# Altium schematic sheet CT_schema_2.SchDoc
size 461 x 297 mm
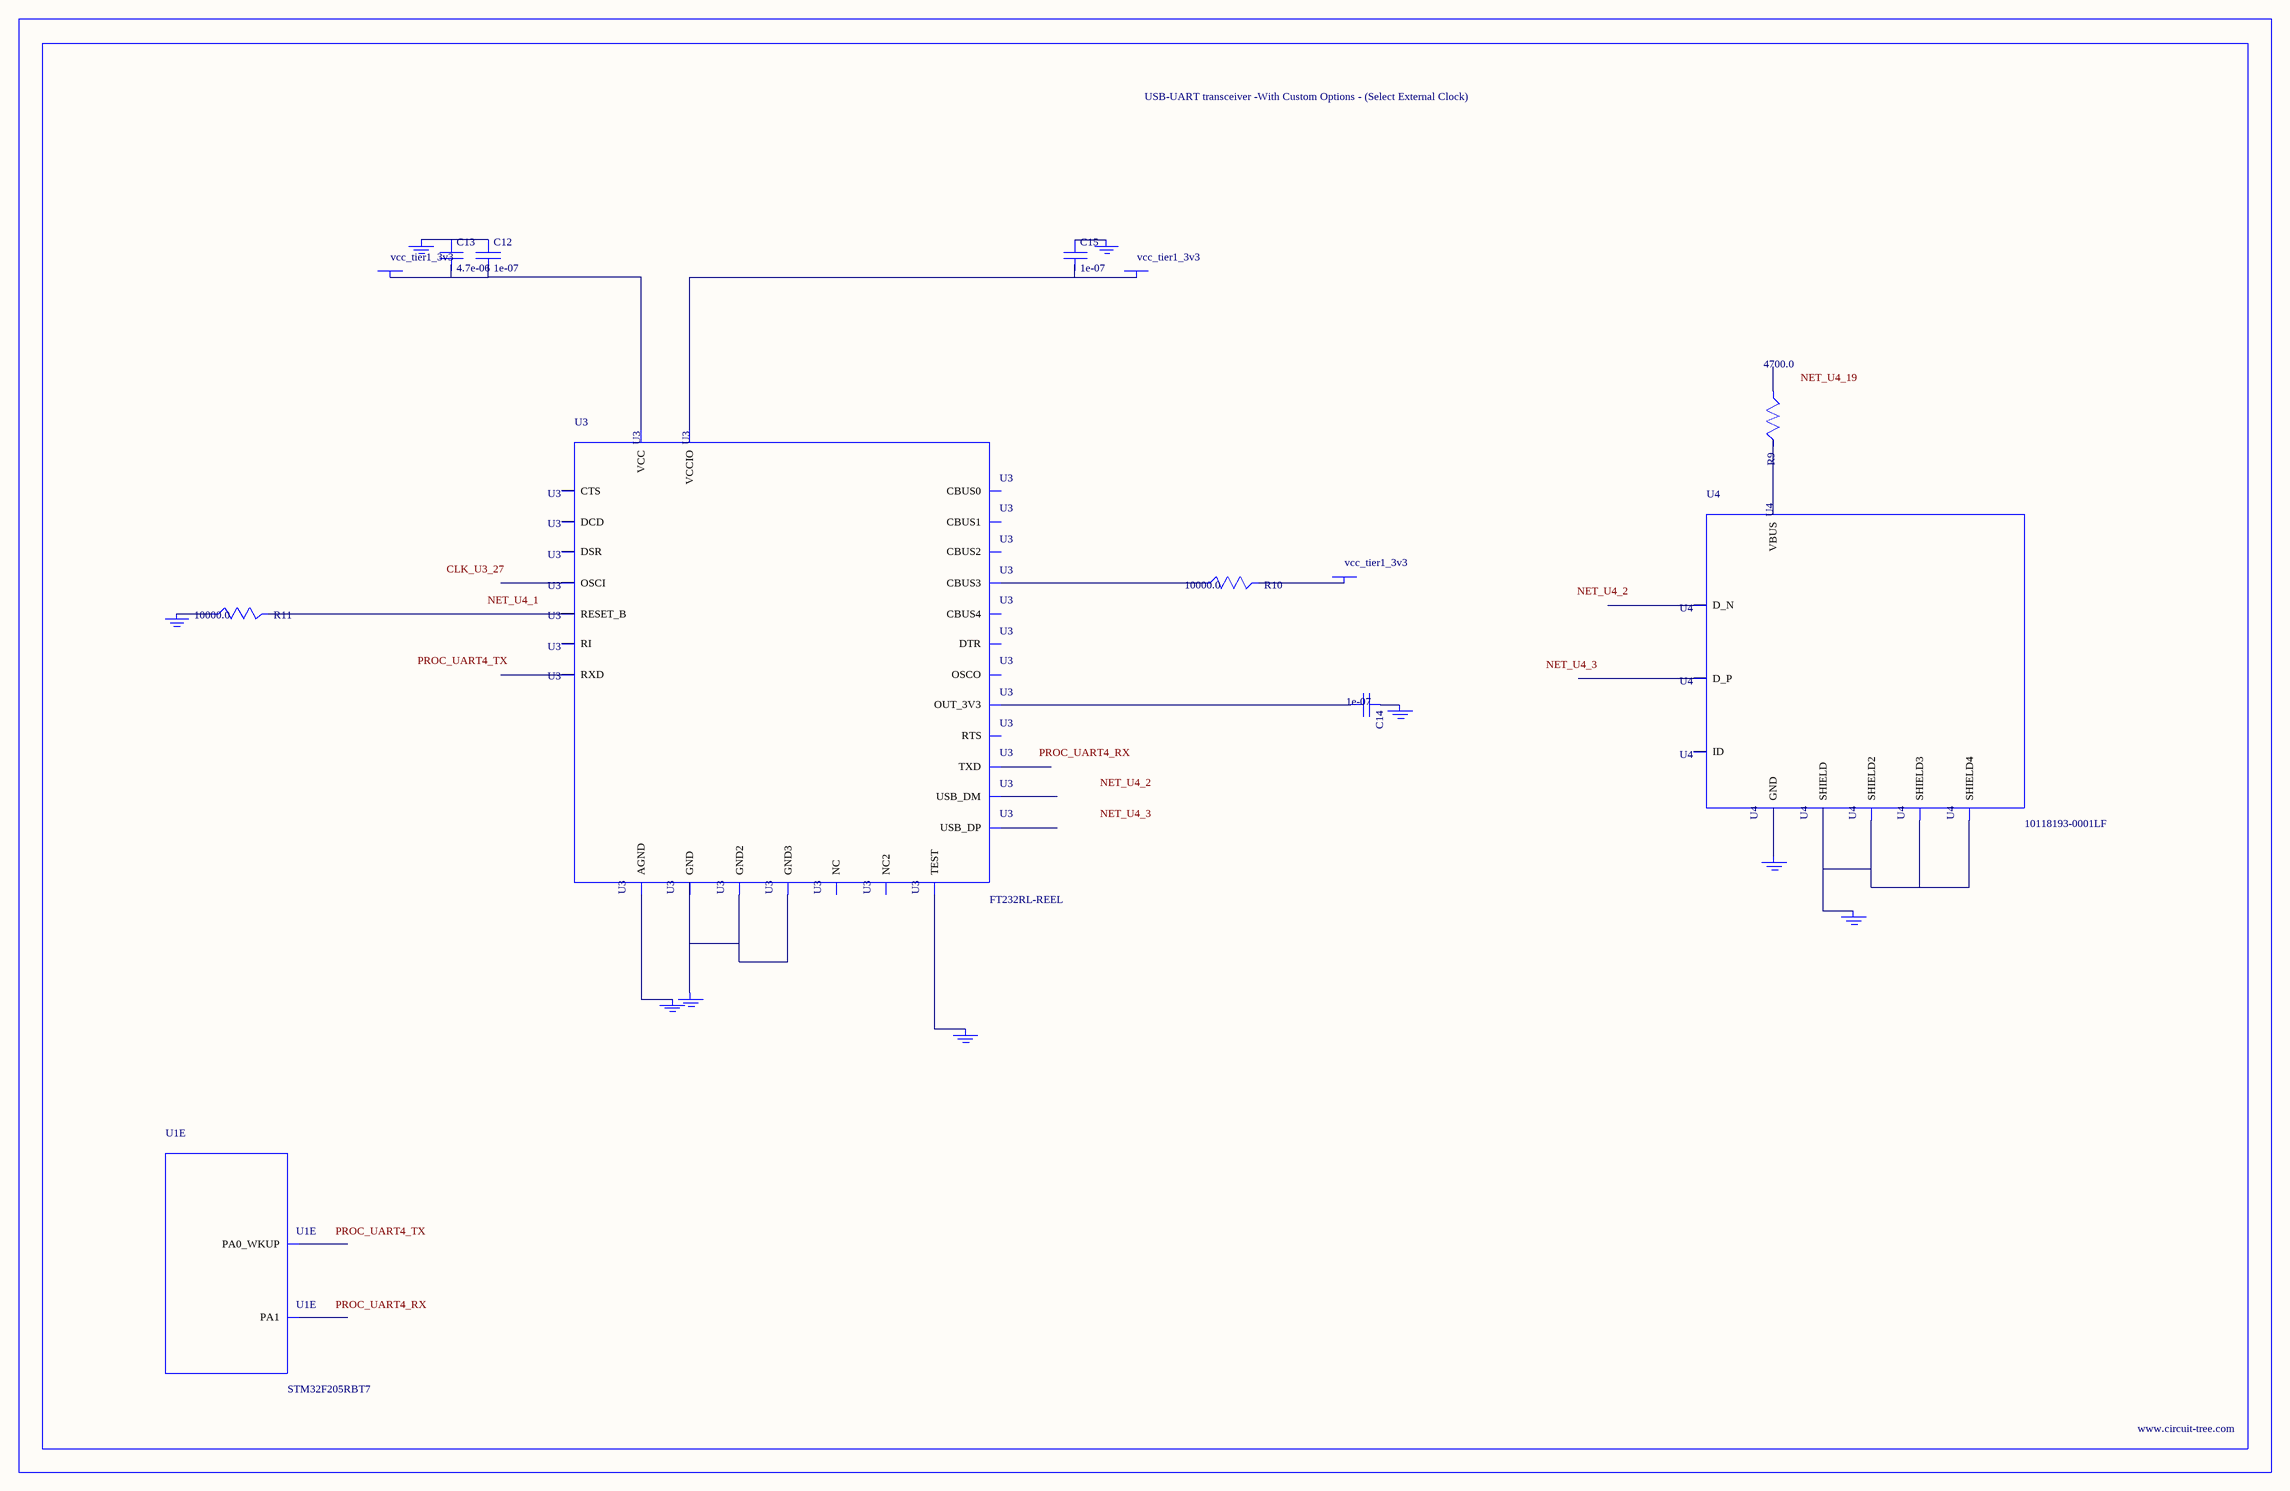
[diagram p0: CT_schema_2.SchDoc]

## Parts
BORDER1  (no value)
C12  1e-07  [C0402]
C13  4.7e-06  [C0805]
C14  1e-07  [C0402]
C15  1e-07  [C0402]
GND_INSTANCE_1_0  (no value)
GND_INSTANCE_1_1  (no value)
GND_INSTANCE_1_2  (no value)
GND_INSTANCE_1_3  (no value)
GND_INSTANCE_1_4  (no value)
GND_INSTANCE_1_5  (no value)
GND_INSTANCE_1_6  (no value)
GND_INSTANCE_1_7  (no value)
GND_INSTANCE_1_8  (no value)
POWER_INSTANCE_1_0  vcc_tier1_3v3
POWER_INSTANCE_1_1  vcc_tier1_3v3
POWER_INSTANCE_1_2  vcc_tier1_3v3
R9  4700.0  [R0603]
R10  10000.0  [R0603]
R11  10000.0  [R0603]
U1  STM32F205RBT7  [LQFP64]  (part E of 7)
U3  FT232RL-REEL  [SSOP-28]
U4  10118193-0001LF  [FCI_10118193-0001LF]

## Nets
NetC12_1: C12.1 C13.1 GND_INSTANCE_1_3.0(GND)
NetC12_2: C12.2 C13.2 POWER_INSTANCE_1_2.0(PWR) U3.20(VCC)
NetC14_1: C14.1 GND_INSTANCE_1_1.0(GND)
NetC14_2: C14.2 U3.17(OUT_3V3)
NetC15_1: C15.1 GND_INSTANCE_1_0.0(GND)
NetC15_2: C15.2 POWER_INSTANCE_1_0.0(PWR) U3.4(VCCIO)
NetGND_INSTANCE_1_2_0: GND_INSTANCE_1_2.0(GND) R11.1
NetGND_INSTANCE_1_4_0: GND_INSTANCE_1_4.0(GND) U3.25(AGND)
NetGND_INSTANCE_1_5_0: GND_INSTANCE_1_5.0(GND) U3.26(TEST)
NetGND_INSTANCE_1_6_0: GND_INSTANCE_1_6.0(GND) U3.7(GND) U3.18(GND2) U3.21(GND3)
NetGND_INSTANCE_1_7_0: GND_INSTANCE_1_7.0(GND) U4.6(SHIELD) U4.7(SHIELD2) U4.8(SHIELD3) U4.9(SHIELD4)
NetGND_INSTANCE_1_8_0: GND_INSTANCE_1_8.0(GND) U4.5(GND)
NetPOWER_INSTANCE_1_1_0: POWER_INSTANCE_1_1.0(PWR) R10.2
NetR9_2: R9.2 U4.1(VBUS)
NetR10_1: R10.1 U3.14(CBUS3)
NetR11_2: R11.2 U3.19(RESET_B)

Not connected (* = marked no-connect by the designer): R9 1; U1 14(PA0_WKUP) 15(PA1); U3 1(TXD) 2(DTR) 3(RTS) 5(RXD) 6(RI) 8(NC) 9(DSR) 10(DCD) 11(CTS) 12(CBUS4) 13(CBUS2) 15(USB_DP) 16(USB_DM) 22(CBUS1) 23(CBUS0) 24(NC2) 27(OSCI) 28(OSCO); U4 2(D_N) 3(D_P) 4(ID)

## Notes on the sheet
- Labels drawn without touching a wire or pin: CLK_U3_27, NET_U4_1, NET_U4_2, NET_U4_3, NET_U4_19, PROC_UART4_RX, PROC_UART4_TX

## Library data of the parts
BORDER1 = BORDER_PAGE1
C12 C14 C15 = C0402C104K3RACTU
C13 = C0805C475K4RACTU
GND_INSTANCE_1_0-GND_INSTANCE_1_8 = GND
POWER_INSTANCE_1_0-POWER_INSTANCE_1_2 = PWR
R9 = RC0603JR-074K7L
R10 R11 = RC0603JR-0710KL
